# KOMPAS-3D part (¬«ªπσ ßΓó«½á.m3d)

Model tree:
1. Эскиз:5
2. Операция выдавливания:3
     Расстояние 1 = 10; Угол 1 = 10; Расстояние 2 = 40; Угол 2 = 41
3. Эскиз:6
4. Вырезать элемент выдавливания:4
     Расстояние 2 = 43.1215; Расстояние 1 = 43.1215
5. Эскиз:7
6. Вырезать элемент выдавливания:5
     Расстояние 1 = 34.2699
7. Скругление:6
     Радиус = 2
8. Скругление:7
     Радиус = 2
9. Эскиз:8
10. Вырезать элемент выдавливания:6
     Угол 2 = 4; Расстояние 1 = 34.2699; Угол 1 = 9

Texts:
  stalker61
  Кожа техническая  ГОСТ 20836-75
